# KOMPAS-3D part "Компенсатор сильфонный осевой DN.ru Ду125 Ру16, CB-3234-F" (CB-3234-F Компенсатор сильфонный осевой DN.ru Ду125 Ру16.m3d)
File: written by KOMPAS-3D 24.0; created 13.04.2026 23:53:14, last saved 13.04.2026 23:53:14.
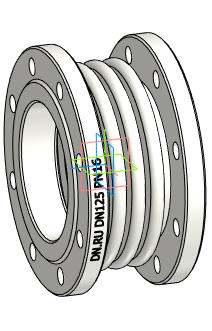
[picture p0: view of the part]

Document properties: Автор: DN.RU; Полное имя файла: D:\PROJECT CAD\DN.RU\...198(ACTUALE). CB-3234-F Компенсатор сильфонный осевой DN.ru\Исходники\DN125\CB-3234-F Компенсатор сильфонный осевой DN.ru Ду125 Ру16.m3d

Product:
- Body: Твердое тело1  | qty 1
    Масса: 13.622219
- Part/product: Компенсатор сильфонный осевой DN.ru Ду125 Ру16  | designation CB-3234-F
    Масса: 10.5
    Раздел спецификации: Прочие изделия
    Комментарий: D140-02117
    Примечание: D140-02117
    additional columns: Типовые

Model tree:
1. Твердое тело1  (labels: Твердое тело1)

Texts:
  CB-3234-F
